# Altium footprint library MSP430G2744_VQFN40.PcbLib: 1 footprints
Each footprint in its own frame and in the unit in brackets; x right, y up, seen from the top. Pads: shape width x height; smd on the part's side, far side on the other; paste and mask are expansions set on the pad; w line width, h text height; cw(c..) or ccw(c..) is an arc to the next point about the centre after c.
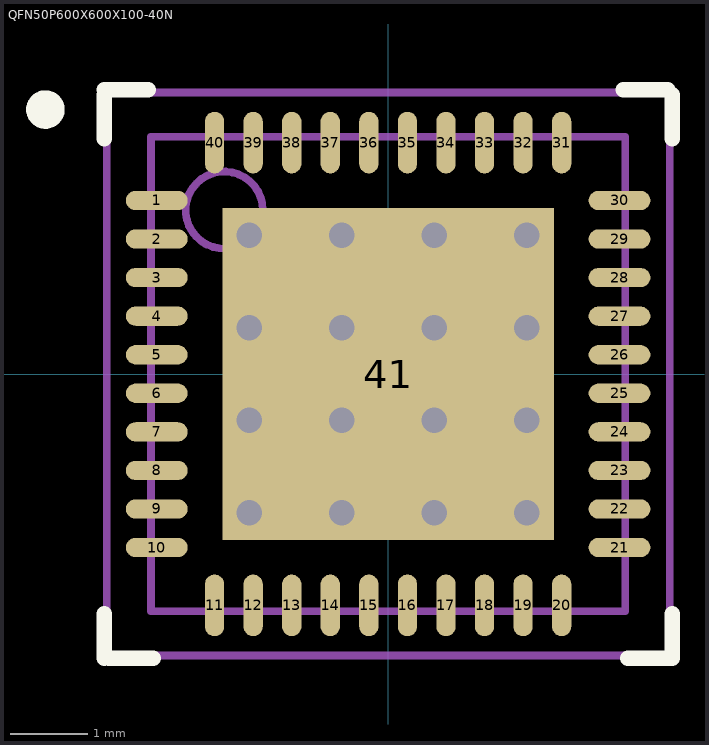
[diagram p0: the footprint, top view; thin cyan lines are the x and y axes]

## QFN50P600X600X100-40N [mm] "QFN, 40-Leads, Body 6.2x6.2mm (max), Pitch 0.50mm, IPC Medium Density"
height 1
pads (41):
  oval 0.8x0.25 smd: 1(-3,2.25) 2(-3,1.75) 3(-3,1.25) 4(-3,0.75) 5(-3,0.25) 6(-3,-0.25) 7(-3,-0.75) 8(-3,-1.25) 9(-3,-1.75) 10(-3,-2.25) 21(3,-2.25) 22(3,-1.75) 23(3,-1.25) 24(3,-0.75) 25(3,-0.25) 26(3,0.25) 27(3,0.75) 28(3,1.25) 29(3,1.75) 30(3,2.25)
  oval 0.25x0.8 smd: 11(-2.25,-3) 12(-1.75,-3) 13(-1.25,-3) 14(-0.75,-3) 15(-0.25,-3) 16(0.25,-3) 17(0.75,-3) 18(1.25,-3) 19(1.75,-3) 20(2.25,-3) 31(2.25,3) 32(1.75,3) 33(1.25,3) 34(0.75,3) 35(0.25,3) 36(-0.25,3) 37(-0.75,3) 38(-1.25,3) 39(-1.75,3) 40(-2.25,3)
  rect 4.3x4.3 smd: 41(0,0)
via 1.8,-1.8 diameter 0.66 hole 0.33
via 0.6,-1.8 diameter 0.66 hole 0.33
via -0.6,-1.8 diameter 0.66 hole 0.33
via -1.8,-1.8 diameter 0.66 hole 0.33
via 1.8,-0.6 diameter 0.66 hole 0.33
via 0.6,-0.6 diameter 0.66 hole 0.33
via -0.6,-0.6 diameter 0.66 hole 0.33
via -1.8,-0.6 diameter 0.66 hole 0.33
via 1.8,0.6 diameter 0.66 hole 0.33
via 0.6,0.6 diameter 0.66 hole 0.33
via -0.6,0.6 diameter 0.66 hole 0.33
via -1.8,0.6 diameter 0.66 hole 0.33
via 1.8,1.8 diameter 0.66 hole 0.33
via 0.6,1.8 diameter 0.66 hole 0.33
via -0.6,1.8 diameter 0.66 hole 0.33
via -1.8,1.8 diameter 0.66 hole 0.33
Top Overlay:
  circle w0.25: c-4.443,3.429 r0.125
  lines w0.2: -3.683,-3.683 -3.683,-3.108 ; -3.683,3.048 -3.683,3.623 ; -3.683,3.683 -3.108,3.683 ; -3.623,-3.683 -3.048,-3.683 ; 3.048,3.683 3.623,3.683 ; 3.108,-3.683 3.683,-3.683 3.683,-3.108 ; 3.683,3.048 3.683,3.623
Mechanical 13:
  circle w0.1: c-2.125,2.125 r0.5
  lines w0.1: -3.075,-3.075 3.075,-3.075 3.075,3.075 -3.075,3.075 -3.075,-3.075
Mechanical 15:
  lines w0.1: -0.5,0 0.5,0 ; 0,-0.5 0,0.5 ; -3.65,-3.65 3.65,-3.65 3.65,3.65 -3.65,3.65 -3.65,-3.65
3D body: height 1, standoff 0.01, extent -3.075,-3.075 3.075,3.075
